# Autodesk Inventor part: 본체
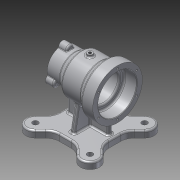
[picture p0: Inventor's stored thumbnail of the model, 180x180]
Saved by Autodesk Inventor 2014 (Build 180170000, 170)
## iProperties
Created: 2017-03
Part Number: 본체
Material: 알루미늄 6061
Document SubType Name: Modeling
Designer: user
Density: 2.71 g/cm^3
Appearance: 알루미늄 - 평지
Mass: 1014.89 g
Surface Area: 847.373 cm^2
Volume: 374.498 cm^3
Author: user
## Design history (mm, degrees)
sketch "스케치2"
  geometry: L1 (-45, 45)-(45, 45); L2 (45, 45)-(45, -45); L3 (45, -45)-(-45, -45); L4 (-45, -45)-(-45, 45); L5 (-49.497, 49.497)-(45, -45); L6 (45, 45)-(-45, -45); L7 (-37.477, 61.518)-(-20.958, 45); L8 (-61.518, 37.477)-(-45, 20.958); L9 (-45, 45)-(49.497, -49.497); L10 (49.497, 49.497)-(-49.497, -49.497); L11 (-61.518, -37.477)-(-45, -20.958); L12 (-37.477, -61.518)-(-20.958, -45); L13 (37.477, -61.518)-(20.958, -45); L14 (37.477, 61.518)-(20.958, 45); L15 (61.518, -37.477)-(45, -20.958); L16 (61.518, 37.477)-(45, 20.958); A1 r 70 centre (0, 0) between (-49.497, 49.497) and (49.497, 49.497); A2 r 17 centre (-49.497, 49.497) between (-37.477, 61.518) and (-61.518, 37.477); A3 r 17 centre (49.497, 49.497) between (37.477, 37.477) and (33.103, 45); A4 r 17 centre (49.497, -49.497) between (37.477, -61.518) and (61.518, -37.477); A5 r 17 centre (-49.497, -49.497) between (-61.518, -37.477) and (-37.477, -61.518); 1 further point
  constraints: 32 end point, 14 point on circle, 14 point on line, 8 tangent, 7 parallel, 5 centre point, 4 perpendicular, 3 coincident, 1 collinear, 1 horizontal, 1 midpoint
  dimensions: "d19" = 90 distance of L2.end L3.end; "d20" = 90 distance of L1.end L2.end; "d21" = 140 diameter of A1; "d24" = 34 diameter of A2; "d29" = 34 diameter of A3; "d30" = 34 diameter of A4; "d32" = 34 diameter of A5
extrude "돌출2" new body sketch "스케치2" distance "d22" = 12; taper "d23" = 0 deg
extrude "돌출3" join sketch "스케치2" distance "d25" = 12; taper "d26" = 0 deg
extrude "돌출4" join sketch "스케치2" distance "d27" = 12; taper "d28" = 0 deg
extrude "돌출5" cut sketch "스케치2" distance "d41" = 12; taper "d42" = 0 deg
extrude "돌출6" join sketch "스케치2" distance "d43" = 12; taper "d44" = 0 deg
fillet "모깎기1" dims "d45" = 25
fillet "모깎기2" dims "d46" = 25
sketch "스케치3"
  geometry: C1 r 5 at (-49.497, 49.497); C2 r 5 at (49.497, 49.497); C3 r 5 at (49.497, -49.497); C4 r 5 at (-49.497, -49.497); A1 r 17 centre (49.497, -49.497) between (37.477, -61.518) and (61.518, -37.477) reference; A2 r 17 centre (49.497, 49.497) between (61.518, 37.477) and (37.477, 61.518) reference; A3 r 17 centre (-49.497, 49.497) between (-37.477, 61.518) and (-61.518, 37.477) reference; A4 r 17 centre (-49.497, -49.497) between (-61.518, -37.477) and (-37.477, -61.518) reference; 1 further point
  constraints: 4 centre point, 4 coincident
  dimensions: "d47" = 10 diameter of C1; "d48" = 10 diameter of C2; "d49" = 10 diameter of C3; "d50" = 10 diameter of C4
extrude "돌출7" cut sketch "스케치3" distance "d51" = 12; taper "d52" = 0 deg
sketch "스케치4"
  geometry: L1 (-50, 82)-(50, 82); L2 (10.603, 0)-(-10.603, 0) reference; L3 (-50, 82)-(-50, 127); L4 (-50, 127)-(-30, 127); L5 (-30, 127)-(-19, 118); L6 (-19, 118)-(15, 118); L7 (15, 118)-(27, 109.5); L8 (27, 109.5)-(50, 109.5); L9 (50, 109.5)-(50, 82); 3 further points
  constraints: 16 end point, 3 perpendicular, 2 midpoint, 2 parallel, 1 horizontal, 1 vertical alignment
  dimensions: "d53" = 82 distance between parallel lines of L1 L2; "d54" = 90 diameter of L4 L1; "d55" = 20 distance of L3.end L4.end; "d56" = 72 diameter of L6 L1; "d57" = 55 diameter of L8 L1; "d58" = 31 distance from line of L5.end L3; "d59" = 65 distance from line of L6.end L3; "d60" = 100 distance between parallel lines of L9 L3; "d61" = 23 distance from line of L7.end L9
revolve "회전1" sketch "스케치4" stored, may be unused: angle "d62" = 90 deg
sketch "스케치5"
  geometry: L1 (-37, 4)-(37, 4); L2 (37, 4)-(37, -4); L3 (37, -4)-(-37, -4); L4 (-37, -4)-(-37, 4); L5 (-37, 4)-(37, -4); L6 (37, 4)-(-37, -4); L7 (4, 25)-(-4, 25); L8 (-4, 25)-(-4, -25); L9 (-4, -25)-(4, -25); L10 (4, -25)-(4, 25); L11 (4, 25)-(-4, -25); L12 (-4, 25)-(4, -25); 1 further point
  constraints: 24 end point, 4 midpoint, 4 parallel, 2 horizontal, 2 perpendicular
  dimensions: "d63" = 74 distance of L2.end L3.end; "d64" = 8 distance of L1.end L2.end; "d69" = 8 distance of L9.end L8.end; "d70" = 50 distance of L8.end L7.end
extrude "돌출9" join sketch "스케치5" stored distance "d71" = 12; taper "d72" = 0 deg
node "작업 평면1"
sketch "스케치7"
  geometry: L1 (50, 45)-(50, -45) reference; C1 r 5 at (0, 0); 2 further points
  constraints: 1 centre point, 1 horizontal alignment, 1 midpoint
  dimensions: "d75" = 10 diameter of C1; "d76" = 50 distance from line of C1.centre L1
extrude "돌출10" join sketch "스케치7" stored distance "d77" = 12; taper "d78" = 0 deg
sketch "스케치8"
  geometry: L1 (-50, 37)-(-50, 127) reference; L2 (-30, 37.178)-(-30, 37.178) reference; L3 (-30, 37.178)-(-37, 37.178) reference; L4 (-37, 37.178)-(-37, 37.178) reference; L5 (-37, 37.178)-(-30, 37.178) reference; L6 (50, 54.5)-(50, 109.5) reference; L7 (-50, 82)-(50, 82); L8 (-27, 114)-(-27, 111); L9 (-24, 108)-(17, 108); L10 (20, 105)-(20, 102.5); L11 (23, 99.5)-(50, 99.5); L12 (-30, 117)-(-50, 117); A1 r 3 centre (-30, 114) between (-27, 114) and (-30, 117); A2 r 3 centre (-24, 111) between (-27, 111) and (-24, 108); A3 r 3 centre (17, 105) between (20, 105) and (17, 108); A4 r 3 centre (23, 102.5) between (20, 102.5) and (23, 99.5); 5 further points
  constraints: 12 end point, 10 point on line, 8 point on circle, 8 tangent, 4 centre point, 4 perpendicular, 3 equal radius, 2 midpoint, 1 parallel
  dimensions: "d80" = 70 diameter of L12 L7; "d81" = 23 distance of point (-27, 117) L12.end; "d82" = 52 diameter of L9 L7; "d83" = 47 distance of point (-27, 108) point (20, 108); "d84" = 35 diameter of L11 L7; "d85" = 30 distance of point (20, 99.5) L11.end (derived); "d86" = 3 radius of A1
revolve "회전2" sketch "스케치8" stored, may be unused: angle "d87" = 90 deg
sketch "스케치9" dims "d88" = 80
  geometry: C1 r 35 at (0, 0) reference; C2 r 45 at (0, 0) reference; 3 further points
  constraints: 2 horizontal alignment, 1 coincident, 2 other
hole "구멍1" sketch "스케치9" at (-40, 0) diameter "d89" = 3.242; stored, may be unused: countersink angle "d93" = 90 deg, drill point angle "d95" = 118 deg; dims "d90" = 9, "d91" = 4, "d92" = 2, "d94" = 11
fillet "모깎기3" dims "d99" = 3
fillet "모깎기4" dims "d100" = 3
chamfer "모따기1" distance "d101" = 1; stored, may be unused: second distance "d102" = 2, angle "d103" = 45 deg
sketch "스케치10"
  geometry: C1 r 7 at (27.5, 0); 2 further points
  constraints: 2 horizontal alignment, 1 centre point, 1 other
  dimensions: "d107" = 7 radius of C1
extrude "돌출11" join sketch "스케치10" distance "d108" = 15; taper "d109" = 0 deg
fillet "모깎기8" dims "d110" = 3
fillet "모깎기9" dims "d111" = 1
sketch "스케치11"
  geometry: A1 r 7 centre (0, 0) between (-0.127, -6.999) and (-0.127, 6.999) reference; 2 further points
  constraints: 1 coincident
hole "구멍2" sketch "스케치11" at (0, 0) diameter "d115" = 3.242; stored, may be unused: countersink angle "d119" = 90 deg, drill point angle "d121" = 118 deg; dims "d116" = 9, "d117" = 4, "d118" = 2, "d120" = 11
sketch "스케치12"
  geometry: C1 r 5 at (0, 0) reference; C2 r 2.5 at (0, 0)
  constraints: 1 centre point, 1 coincident
  dimensions: "d125" = 5 diameter of C2
extrude "돌출12" cut sketch "스케치12" stored distance "d126" = 15; taper "d127" = 0 deg
feature "스레드1" dims "d128" = 10, "d129" = 0
sketch "스케치13"
  geometry: L1 (-45, -10.603)-(-45, 10.603) reference; 2 further points
  constraints: 1 other
  dimensions: "d131" = 35 distance of point (0, 35) point (0, 0); "d132" = 45 distance from line of point (0, 35) L1
feature "엠보싱1" sketch "스케치13" dims "d133" = 0.5, "d134" = 0
feature "면 기울기2" dims angle "d135" = 10 deg
feature "면 기울기3" dims angle "d136" = 10 deg
fillet "모깎기11" dims "d137" = 3
fillet "모깎기12" dims "d138" = 3
fillet "모깎기13" dims "d139" = 3
fillet "모깎기14" dims "d140" = 3
node "솔리드2"
pattern_circular "원형 패턴1" dims angle "d97" = 360 deg
pattern_circular "원형 패턴2" dims "d113" = 360 deg
pattern_circular "원형 패턴3" dims angle "d123" = 360 deg
node "투영된 루프2"
other parameters: "d74" = -122
